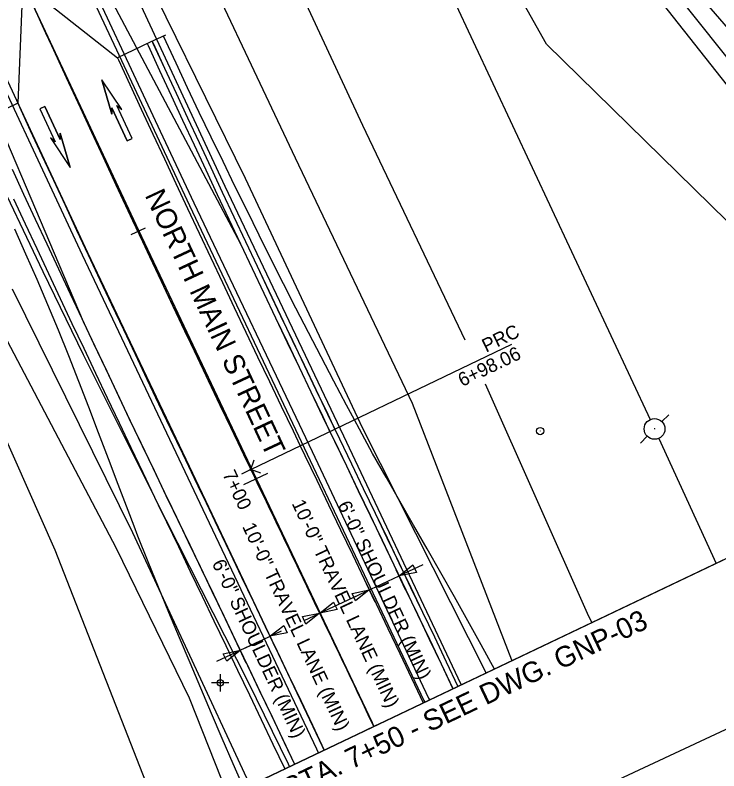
# Model space of a CAD drawing. Extents: x 1040364 to 1041050, y 1127298 to 1128100.
# Drawn here: x 1040771.9 to 1040900.2, y 1127434.3 to 1127572.2 of the extents above; entities that cross this region are included whole.
import ezdxf

# ---------------------------------------------------------------- set-up
doc = ezdxf.new("R2010")
doc.units = 0
for name, color, linetype in [('AC_P', 7, 'Continuous'), ('ACP_P', 7, 'Continuous'), ('ACSC_P_T', 7, 'Continuous'), ('ACSCT_P', 7, 'Continuous'), ('ACSR_P_T', 7, 'Continuous'), ('ACSRT_P', 7, 'Continuous'), ('clip boundary', 7, 'Continuous'), ('DELB', 7, 'Continuous'), ('LELB', 7, 'Continuous'), ('LFILL_P', 7, 'Continuous'), ('LPST', 7, 'Continuous'), ('NML_P', 7, 'Continuous'), ('NML_P_T', 7, 'Continuous'), ('O_Details_Dimensions_Extension_Lines_P', 7, 'Continuous'), ('O_Details_Text Title and Subtitle Proposed_P_T', 7, 'Continuous'), ('PE', 7, 'Continuous'), ('PE_P', 7, 'Continuous'), ('PET_P', 7, 'Continuous'), ('PSCL_P', 7, 'Continuous'), ('RBS_P', 7, 'Continuous'), ('RGB_P', 7, 'Continuous'), ('RGC', 7, 'Continuous'), ('S', 7, 'Continuous'), ('SHEET_BORDER', 7, 'Continuous'), ('STFBY', 7, 'Continuous'), ('STFBY_P', 7, 'Continuous'), ('STSEW', 7, 'Continuous'), ('STSEY_P_T', 7, 'Continuous'), ('UEO', 7, 'Continuous'), ('UP', 7, 'Continuous')]:
    doc.layers.add(name, color=color, linetype=linetype)

msp = doc.modelspace()

# ---------------------------------------------------------------- linework, layer by layer
at = {"layer": 'AC_P'}
for centre, radius, start, end in [((1045321.32, 1129655.39), 5000, 200.40109, 205.67201), ((1027295.55, 1120991.01), 15000, 25.473615, 25.672008)]:
    msp.add_arc(centre, radius, start, end, dxfattribs=at)
at = {"layer": 'ACP_P'}
for p, q in [((1040814.88, 1127489.29), (1040815.5, 1127491.07)), ((1040814.88, 1127489.29), (1040813.18, 1127488.48)), ((1040816.66, 1127488.67), (1040814.88, 1127489.29))]:
    msp.add_line(p, q, dxfattribs=at)
msp.add_circle((1040814.88, 1127489.29), 0.154, dxfattribs=at)
at = {"layer": 'ACSCT_P'}
msp.add_lwpolyline([(1040814.88, 1127489.29), (1040862.47, 1127512.17)], dxfattribs=at)
at = {"layer": 'ACSRT_P'}
for points in [[(1040795.57, 1127533.32), (1040792.96, 1127532.1)], [(1040817.88, 1127488.58), (1040813.55, 1127486.5)], [(1040838.6, 1127443.06), (1040836, 1127441.82)]]:
    msp.add_lwpolyline(points, dxfattribs=at)
at = {"layer": 'clip boundary'}
msp.add_lwpolyline([(1040504.79, 1127904.67), (1040760.34, 1127999.71), (1040984.84, 1127512.73), (1040710.81, 1127382.18)], close=True, dxfattribs=at)
at = {"layer": 'DELB'}
for points in [[(1040843.18, 1127644.23), (1040860.99, 1127621.14), (1040885.95, 1127579.46), (1040912.52, 1127545.72), (1040920.83, 1127536.22), (1040925.1, 1127538.74), (1040927.41, 1127544.76), (1040923.92, 1127547.39), (1040891.85, 1127585.59), (1040869.69, 1127619.79), (1040852.79, 1127648.53), (1040846.95, 1127649.39), (1040843.18, 1127644.23)], [(1040848.54, 1127644.26), (1040847.59, 1127642.87), (1040862.62, 1127622.4), (1040888.43, 1127581.11), (1040915.18, 1127547.57), (1040922.33, 1127543.57), (1040922.43, 1127546.09), (1040889.43, 1127584.33), (1040867.88, 1127618.82), (1040850.55, 1127644.3), (1040848.54, 1127644.26)]]:
    msp.add_lwpolyline(points, dxfattribs=at)
at = {"layer": 'LELB'}
for points in [[(1040810.73, 1127429.78), (1040803.7, 1127447.62), (1040790.28, 1127475.04), (1040767.31, 1127518.61), (1040755.95, 1127542.69), (1040738.89, 1127579.03), (1040723.86, 1127612.81), (1040706.92, 1127651.68), (1040695, 1127676.62), (1040683.43, 1127703.39), (1040670.93, 1127728.26), (1040660.81, 1127750.01), (1040651.71, 1127772.02), (1040637.02, 1127804.07), (1040629.69, 1127830.98), (1040616.26, 1127871.74), (1040612.35, 1127873.83), (1040609.66, 1127871.77), (1040608.53, 1127867.34), (1040606.04, 1127852.48)], [(1040713.7, 1127825.26), (1040727.06, 1127775.17), (1040743.3, 1127730.12), (1040761.87, 1127681.6), (1040780.54, 1127637.65), (1040801.46, 1127591.59), (1040822.93, 1127546.17), (1040844.27, 1127501.4), (1040862.43, 1127454.57), (1040862.49, 1127454.44)], [(1040733.39, 1127778.3), (1040755.39, 1127731.1), (1040772.83, 1127689.2), (1040794.16, 1127643.36), (1040815.07, 1127595.54), (1040835.22, 1127552.16), (1040853.9, 1127512.99)], [(1040857.81, 1127452.21), (1040835.32, 1127496.78), (1040813.91, 1127542.4), (1040792.2, 1127586.64), (1040772.38, 1127632.65), (1040752.78, 1127677.66), (1040736.76, 1127724.02), (1040719.71, 1127771.8)], [(1040931.31, 1127487.23), (1040907.7, 1127528.76), (1040868.8, 1127566.91), (1040846.16, 1127607.17), (1040843.18, 1127644.23)], [(1040814.73, 1127431.69), (1040814.14, 1127433.03), (1040793.33, 1127477.77), (1040771.38, 1127522.24)], [(1040759.32, 1127519.12), (1040779.14, 1127474.66), (1040797.84, 1127426.8), (1040798.87, 1127424.14)], [(1040857.64, 1127504.94), (1040876.45, 1127462.54), (1040877.08, 1127461.4)]]:
    msp.add_lwpolyline(points, dxfattribs=at)
at = {"layer": 'LFILL_P'}
for points in [[(1040859.29, 1127452.92), (1040856.87, 1127457.31), (1040854.44, 1127461.7), (1040851.99, 1127466.08), (1040849.52, 1127470.45), (1040847.04, 1127474.82), (1040844.54, 1127479.17), (1040842.03, 1127483.52), (1040839.55, 1127487.89), (1040837.07, 1127492.25), (1040834.67, 1127496.65), (1040833.75, 1127498.36), (1040832.32, 1127501.06), (1040829.99, 1127505.46), (1040827.68, 1127509.88), (1040825.38, 1127514.3), (1040823.1, 1127518.73), (1040820.84, 1127523.17), (1040818.6, 1127527.62), (1040816.37, 1127532.07), (1040814.17, 1127536.54), (1040811.97, 1127541.01), (1040809.79, 1127545.49), (1040807.62, 1127549.97), (1040805.47, 1127554.47), (1040803.34, 1127558.97), (1040801.22, 1127563.47), (1040798.92, 1127568.38)], [(1040771.75, 1127533.24), (1040773.79, 1127528.65), (1040775.81, 1127524.05), (1040777.78, 1127519.43), (1040779.73, 1127514.8), (1040781.58, 1127510.12), (1040783.41, 1127505.43), (1040785.23, 1127500.74), (1040787.04, 1127496.04), (1040788.84, 1127491.33), (1040790.63, 1127486.62), (1040792.43, 1127481.91), (1040793.53, 1127479.03), (1040794.22, 1127477.22), (1040796.05, 1127472.55), (1040797.94, 1127467.93), (1040799.86, 1127463.31), (1040801.78, 1127458.69), (1040803.71, 1127454.09), (1040805.66, 1127449.48), (1040807.61, 1127444.88), (1040809.58, 1127440.29), (1040811.57, 1127435.71), (1040813.59, 1127431.15)]]:
    msp.add_lwpolyline(points, dxfattribs=at)
at = {"layer": 'LPST'}
for p, q in [((1040867.65, 1127496.35), (1040867.62, 1127496.32)), ((1040867.62, 1127496.35), (1040867.65, 1127496.32))]:
    msp.add_line(p, q, dxfattribs=at)
msp.add_circle((1040867.64, 1127496.33), 0.658, dxfattribs=at)
at = {"layer": 'NML_P'}
msp.add_line((1040710.81, 1127382.18), (1040984.84, 1127512.73), dxfattribs=at)
at = {"layer": 'O_Details_Dimensions_Extension_Lines_P'}
for p, q in [((1040843.1, 1127467.37), (1040841.39, 1127471.03)), ((1040846.27, 1127471.93), (1040841.92, 1127469.9)), ((1040833.65, 1127466.03), (1040841.92, 1127469.9)), ((1040837.54, 1127465.09), (1040835.96, 1127468.49)), ((1040827.42, 1127463.12), (1040834.31, 1127466.34)), ((1040828.7, 1127460.4), (1040826.9, 1127464.26)), ((1040824.59, 1127461.8), (1040827.46, 1127463.14)), ((1040813.87, 1127456.79), (1040820.45, 1127459.86)), ((1040819.47, 1127456.53), (1040817.83, 1127460.02)), ((1040814.02, 1127454), (1040812.39, 1127457.5)), ((1040812.93, 1127456.34), (1040816.55, 1127458.05)), ((1040808.64, 1127454.33), (1040812.99, 1127456.36))]:
    msp.add_line(p, q, dxfattribs=at)
for points in [[(1040845.07, 1127470.54), (1040841.92, 1127469.9), (1040844.44, 1127471.9)], [(1040833.33, 1127466.71), (1040836.48, 1127467.36), (1040833.97, 1127465.35)], [(1040830.61, 1127463.78), (1040827.46, 1127463.14), (1040829.97, 1127465.14)], [(1040824.27, 1127462.48), (1040827.42, 1127463.12), (1040824.91, 1127461.12)], [(1040821.51, 1127459.53), (1040818.36, 1127458.89), (1040820.88, 1127460.89)], [(1040809.84, 1127455.72), (1040812.99, 1127456.36), (1040810.48, 1127454.36)]]:
    msp.add_lwpolyline(points, close=True, dxfattribs=at)
at = {"layer": 'O_Details_Text Title and Subtitle Proposed_P_T'}
for p, q in [((1040789.5, 1127554.17), (1040787.7, 1127560.39)), ((1040791.32, 1127555.01), (1040787.7, 1127560.39)), ((1040776.83, 1127555.31), (1040776.8, 1127555.3)), ((1040776.84, 1127555.29), (1040776.81, 1127555.28)), ((1040790.44, 1127555.71), (1040791.32, 1127555.01)), ((1040780.11, 1127550.66), (1040781.91, 1127544.44)), ((1040778.29, 1127549.81), (1040781.91, 1127544.44)), ((1040779.17, 1127549.12), (1040778.29, 1127549.81)), ((1040792.77, 1127549.53), (1040792.8, 1127549.55)), ((1040792.78, 1127549.52), (1040792.81, 1127549.53))]:
    msp.add_line(p, q, dxfattribs=at)
at = {"layer": 'PE'}
for points in [[(1040632.25, 1127952.07), (1040649.62, 1127906.04), (1040655.5, 1127890.52), (1040667.36, 1127859.52), (1040679.42, 1127828.44), (1040685.53, 1127812.93), (1040691.68, 1127797.52), (1040704.12, 1127766.75), (1040723.07, 1127720.54), (1040735.94, 1127689.83), (1040742.48, 1127674.51), (1040755.79, 1127643.96), (1040762.56, 1127628.73), (1040769.44, 1127613.48), (1040783.38, 1127583.06), (1040797.39, 1127552.96), (1040804.47, 1127537.94), (1040826.05, 1127492.6), (1040847.29, 1127447.58), (1040847.43, 1127447.27)], [(1040827.22, 1127437.64), (1040826.9, 1127438.31), (1040805.61, 1127483.11), (1040784.16, 1127528.43), (1040762.74, 1127574.12), (1040748.8, 1127604.56), (1040741.94, 1127619.83), (1040735.2, 1127635.03), (1040721.93, 1127665.52), (1040708.68, 1127696.59), (1040702.17, 1127712.18), (1040695.93, 1127727.39), (1040683.59, 1127757.86), (1040671.21, 1127788.47), (1040665.07, 1127803.8), (1040658.98, 1127819.2), (1040646.94, 1127850.06), (1040634.62, 1127882.06), (1040628.54, 1127898.1), (1040611.22, 1127944.25)]]:
    msp.add_lwpolyline(points, dxfattribs=at)
at = {"layer": 'PE_P'}
for points in [[(1040795.88, 1127567.13), (1040796.11, 1127566.68), (1040798.23, 1127562.09), (1040800.32, 1127557.57), (1040802.42, 1127553.05), (1040804.53, 1127548.53), (1040806.64, 1127544.01), (1040808.75, 1127539.5), (1040810.87, 1127534.99), (1040812.99, 1127530.48), (1040815.12, 1127525.97), (1040817.25, 1127521.47), (1040819.39, 1127516.96), (1040821.53, 1127512.46), (1040823.67, 1127507.96), (1040825.82, 1127503.47), (1040827.98, 1127498.97), (1040829.3, 1127496.22), (1040830.14, 1127494.47), (1040832.31, 1127489.96), (1040834.47, 1127485.45), (1040836.64, 1127480.94), (1040838.8, 1127476.42), (1040840.96, 1127471.91), (1040843.12, 1127467.39), (1040845.28, 1127462.88), (1040847.43, 1127458.36), (1040849.59, 1127453.84), (1040851.74, 1127449.32)], [(1040771.3, 1127544.1), (1040773.41, 1127539.55), (1040775.53, 1127535), (1040777.65, 1127530.46), (1040779.78, 1127525.92), (1040781.91, 1127521.37), (1040784.05, 1127516.84), (1040786.19, 1127512.3), (1040788.33, 1127507.77), (1040790.48, 1127503.23), (1040792.64, 1127498.7), (1040794.8, 1127494.18), (1040796.96, 1127489.65), (1040799.13, 1127485.13), (1040800.46, 1127482.36), (1040801.3, 1127480.61), (1040803.46, 1127476.11), (1040805.62, 1127471.61), (1040807.78, 1127467.11), (1040809.94, 1127462.6), (1040812.09, 1127458.1), (1040814.25, 1127453.59), (1040816.4, 1127449.08), (1040818.55, 1127444.58), (1040820.7, 1127440.07), (1040822.85, 1127435.56)]]:
    msp.add_lwpolyline(points, dxfattribs=at)
at = {"layer": 'PET_P'}
for points in [[(1040790.52, 1127564.43), (1040790.7, 1127564.07), (1040792.78, 1127559.57), (1040794.88, 1127555.04), (1040796.98, 1127550.52), (1040799.09, 1127545.99), (1040801.2, 1127541.47), (1040803.32, 1127536.95), (1040805.44, 1127532.44), (1040807.56, 1127527.92), (1040809.69, 1127523.41), (1040811.83, 1127518.9), (1040813.97, 1127514.39), (1040816.11, 1127509.88), (1040818.26, 1127505.38), (1040820.41, 1127500.88), (1040822.57, 1127496.38), (1040823.89, 1127493.62), (1040824.73, 1127491.87), (1040826.9, 1127487.36), (1040829.06, 1127482.85), (1040831.22, 1127478.34), (1040833.39, 1127473.83), (1040835.55, 1127469.32), (1040837.71, 1127464.8), (1040839.86, 1127460.29), (1040842.02, 1127455.77), (1040844.17, 1127451.26), (1040846.32, 1127446.74)], [(1040772.35, 1127556.12), (1040774.63, 1127551.17), (1040776.74, 1127546.62), (1040778.85, 1127542.08), (1040780.97, 1127537.54), (1040783.09, 1127533), (1040785.21, 1127528.46), (1040787.34, 1127523.93), (1040789.47, 1127519.39), (1040791.61, 1127514.86), (1040793.75, 1127510.33), (1040795.9, 1127505.81), (1040798.05, 1127501.28), (1040800.21, 1127496.76), (1040802.37, 1127492.24), (1040804.54, 1127487.72), (1040805.86, 1127484.96), (1040806.7, 1127483.21), (1040808.87, 1127478.71), (1040811.03, 1127474.2), (1040813.19, 1127469.7), (1040815.35, 1127465.19), (1040817.51, 1127460.69), (1040819.66, 1127456.18), (1040821.82, 1127451.67), (1040823.97, 1127447.16), (1040826.12, 1127442.65), (1040828.27, 1127438.14)]]:
    msp.add_lwpolyline(points, dxfattribs=at)
at = {"layer": 'PSCL_P'}
for p, q in [((1040773.26, 1127578.08), (1040772.35, 1127556.12)), ((1040773.26, 1127578.08), (1040790.52, 1127564.43)), ((1040796.4, 1127567.22), (1040790.52, 1127564.43)), ((1040772.35, 1127556.12), (1040766.62, 1127553.47))]:
    msp.add_line(p, q, dxfattribs=at)
at = {"layer": 'RBS_P'}
msp.add_line((1040799.31, 1127568.56), (1040796.4, 1127567.22), dxfattribs=at)
for points in [[(1040796.79, 1127567.55), (1040797.01, 1127567.1), (1040799.13, 1127562.51), (1040801.23, 1127557.99), (1040803.33, 1127553.47), (1040805.43, 1127548.95), (1040807.54, 1127544.44), (1040809.66, 1127539.92), (1040811.78, 1127535.41), (1040813.9, 1127530.9), (1040816.03, 1127526.4), (1040818.16, 1127521.89), (1040820.29, 1127517.39), (1040822.43, 1127512.89), (1040824.58, 1127508.39), (1040826.73, 1127503.89), (1040828.88, 1127499.4), (1040830.2, 1127496.65), (1040831.04, 1127494.9), (1040833.21, 1127490.38), (1040835.38, 1127485.87), (1040837.54, 1127481.36), (1040839.7, 1127476.84), (1040841.86, 1127472.33), (1040844.02, 1127467.81), (1040846.18, 1127463.3), (1040848.34, 1127458.78), (1040850.49, 1127454.26), (1040852.64, 1127449.75)], [(1040771.6, 1127538.71), (1040773.72, 1127534.16), (1040775.84, 1127529.61), (1040777.97, 1127525.07), (1040780.1, 1127520.52), (1040782.24, 1127515.98), (1040784.38, 1127511.45), (1040786.52, 1127506.91), (1040788.68, 1127502.38), (1040790.83, 1127497.84), (1040792.99, 1127493.31), (1040795.16, 1127488.79), (1040797.32, 1127484.26), (1040798.65, 1127481.49), (1040799.49, 1127479.75), (1040801.66, 1127475.25), (1040803.82, 1127470.74), (1040805.97, 1127466.24), (1040808.13, 1127461.74), (1040810.29, 1127457.23), (1040812.44, 1127452.73), (1040814.6, 1127448.22), (1040816.75, 1127443.71), (1040818.9, 1127439.21), (1040821.05, 1127434.7)]]:
    msp.add_lwpolyline(points, dxfattribs=at)
at = {"layer": 'RGB_P'}
for points in [[(1040784.95, 1127583.36), (1040812.99, 1127530.49), (1040815.11, 1127525.99), (1040817.24, 1127521.49), (1040819.38, 1127516.99), (1040821.51, 1127512.49), (1040823.66, 1127508), (1040825.81, 1127503.5), (1040827.96, 1127499.01), (1040829.28, 1127496.27), (1040830.12, 1127494.52), (1040832.29, 1127490), (1040834.45, 1127485.49), (1040836.62, 1127480.97), (1040838.78, 1127476.46), (1040840.94, 1127471.94), (1040843.1, 1127467.43), (1040845.26, 1127462.91), (1040847.42, 1127458.39), (1040849.57, 1127453.87), (1040851.73, 1127449.35), (1040851.74, 1127449.32)], [(1040760.67, 1127571.78), (1040784.28, 1127516.33), (1040786.42, 1127511.79), (1040788.57, 1127507.25), (1040790.72, 1127502.72), (1040792.88, 1127498.18), (1040795.04, 1127493.65), (1040797.21, 1127489.12), (1040799.38, 1127484.59), (1040800.71, 1127481.82), (1040801.55, 1127480.08), (1040803.71, 1127475.57), (1040805.87, 1127471.07), (1040808.03, 1127466.57), (1040810.19, 1127462.07), (1040812.34, 1127457.56), (1040814.5, 1127453.06), (1040816.65, 1127448.56), (1040818.8, 1127444.05), (1040820.95, 1127439.54), (1040822.85, 1127435.56)]]:
    msp.add_lwpolyline(points, dxfattribs=at)
at = {"layer": 'RGC'}
for points in [[(1040821.91, 1127435.11), (1040821.71, 1127435.54), (1040814.44, 1127450.47), (1040799.42, 1127480.1), (1040784.36, 1127510.25), (1040776.98, 1127525.39), (1040767.39, 1127545.45), (1040762.66, 1127555.51), (1040755.68, 1127570.65), (1040748.81, 1127585.88), (1040735.39, 1127616.49), (1040722.27, 1127647.33), (1040715.84, 1127662.8), (1040696.64, 1127709.35), (1040677.37, 1127755.44), (1040658.12, 1127800.96), (1040638.6, 1127847.62), (1040631.97, 1127863.41)], [(1040714.38, 1127770.91), (1040732.29, 1127723.82), (1040749.62, 1127677.89), (1040755.63, 1127662.08), (1040762.02, 1127646.41), (1040768.42, 1127631.69), (1040775.21, 1127616.41), (1040789.21, 1127586.06), (1040810.12, 1127540.99), (1040831.75, 1127495.43), (1040853.16, 1127450.13), (1040853.21, 1127450.02)]]:
    msp.add_lwpolyline(points, dxfattribs=at)
at = {"layer": 'S'}
for p, q in [((1040809.3, 1127451.99), (1040809.3, 1127448.84)), ((1040810.87, 1127450.41), (1040807.72, 1127450.41))]:
    msp.add_line(p, q, dxfattribs=at)
msp.add_circle((1040809.3, 1127450.41), 0.591, dxfattribs=at)
at = {"layer": 'SHEET_BORDER'}
msp.add_lwpolyline([(1040652.69, 1127325.65), (1040649.37, 1127326.86), (1040384.85, 1127893.12), (1040386.05, 1127896.45), (1040761.49, 1128071.82), (1040764.81, 1128070.62), (1041029.33, 1127504.35), (1041028.12, 1127501.03)], close=True, dxfattribs=at)
at = {"layer": 'STFBY'}
msp.add_lwpolyline([(1040837.33, 1127442.46), (1040837.03, 1127443.08), (1040815.99, 1127487.47), (1040794.41, 1127532.94), (1040773.27, 1127578.07), (1040759.07, 1127608.84), (1040752.08, 1127624.28), (1040745.3, 1127639.51), (1040732.01, 1127670.09), (1040712.44, 1127716.22), (1040699.8, 1127746.64), (1040693.6, 1127761.89), (1040675.04, 1127808.28), (1040673.1, 1127813.03)], dxfattribs=at)
at = {"layer": 'STFBY_P'}
for points in [[(1040775.34, 1127573.54), (1040777.43, 1127568.99), (1040779.52, 1127564.45), (1040781.61, 1127559.91), (1040783.71, 1127555.37), (1040785.81, 1127550.83), (1040787.92, 1127546.3), (1040790.03, 1127541.77), (1040792.14, 1127537.24), (1040794.26, 1127532.71), (1040796.39, 1127528.18), (1040798.52, 1127523.66), (1040800.65, 1127519.14), (1040802.79, 1127514.62), (1040804.93, 1127510.1), (1040807.08, 1127505.58), (1040809.23, 1127501.07), (1040811.39, 1127496.56), (1040813.55, 1127492.05), (1040814.88, 1127489.29), (1040815.72, 1127487.54), (1040817.88, 1127483.04), (1040820.05, 1127478.53), (1040822.21, 1127474.02), (1040824.37, 1127469.51), (1040826.53, 1127465), (1040828.68, 1127460.49), (1040830.84, 1127455.98), (1040832.99, 1127451.47), (1040835.15, 1127446.95), (1040837.3, 1127442.44)], [(1040796.79, 1127567.54), (1040797.02, 1127567.09), (1040799.14, 1127562.51), (1040801.23, 1127557.98), (1040803.33, 1127553.46), (1040805.44, 1127548.95), (1040807.55, 1127544.43), (1040809.66, 1127539.92), (1040811.78, 1127535.4), (1040813.9, 1127530.9), (1040816.03, 1127526.39), (1040818.16, 1127521.88), (1040820.3, 1127517.38), (1040822.44, 1127512.88), (1040824.58, 1127508.38), (1040826.73, 1127503.88), (1040828.89, 1127499.39), (1040830.21, 1127496.64), (1040831.05, 1127494.89), (1040833.22, 1127490.38), (1040835.38, 1127485.86), (1040837.54, 1127481.35), (1040839.71, 1127476.84), (1040841.87, 1127472.32), (1040844.03, 1127467.81), (1040846.19, 1127463.29), (1040848.34, 1127458.77), (1040850.5, 1127454.26), (1040852.64, 1127449.75)]]:
    msp.add_lwpolyline(points, dxfattribs=at)
at = {"layer": 'STSEW'}
for points in [[(1040631.23, 1127951.69), (1040648.51, 1127905.59), (1040654.39, 1127890.06), (1040666.38, 1127859.09), (1040684.56, 1127812.57), (1040690.71, 1127797.15), (1040703.13, 1127766.35), (1040715.7, 1127735.48), (1040722.06, 1127720.07), (1040728.5, 1127704.72), (1040741.59, 1127674.11), (1040754.93, 1127643.58), (1040761.69, 1127628.35), (1040768.56, 1127613.09), (1040782.51, 1127582.66), (1040803.66, 1127537.47), (1040825.13, 1127492.13), (1040846.44, 1127447.18), (1040846.59, 1127446.87)], [(1040828.27, 1127438.14), (1040827.96, 1127438.8), (1040806.65, 1127483.62), (1040785.12, 1127528.86), (1040763.78, 1127574.53), (1040749.77, 1127604.92), (1040742.86, 1127620.16), (1040736.1, 1127635.32), (1040722.83, 1127665.76), (1040716.16, 1127681.33), (1040702.99, 1127712.55), (1040690.38, 1127742.93), (1040684.16, 1127758.16), (1040671.9, 1127788.75), (1040665.82, 1127804.07), (1040659.73, 1127819.47), (1040647.66, 1127850.31), (1040635.42, 1127882.35), (1040629.38, 1127898.4), (1040612.07, 1127944.56)]]:
    msp.add_lwpolyline(points, dxfattribs=at)
at = {"layer": 'STSEY_P_T'}
for p, q in [((1040791.32, 1127555.01), (1040787.7, 1127560.39)), ((1040787.7, 1127560.39), (1040789.5, 1127554.17)), ((1040777.28, 1127555.52), (1040776.38, 1127555.1)), ((1040776.38, 1127555.1), (1040779.17, 1127549.12)), ((1040776.38, 1127555.1), (1040779.17, 1127549.12)), ((1040777.28, 1127555.52), (1040780.08, 1127549.54)), ((1040780.08, 1127549.54), (1040777.28, 1127555.52)), ((1040789.53, 1127555.28), (1040789.5, 1127554.17)), ((1040789.5, 1127554.17), (1040789.53, 1127555.28)), ((1040792.33, 1127549.3), (1040789.53, 1127555.28)), ((1040789.53, 1127555.28), (1040792.33, 1127549.3)), ((1040793.23, 1127549.73), (1040790.44, 1127555.71)), ((1040793.23, 1127549.73), (1040790.44, 1127555.71)), ((1040790.44, 1127555.71), (1040791.32, 1127555.01)), ((1040780.08, 1127549.54), (1040780.11, 1127550.66)), ((1040780.11, 1127550.66), (1040780.08, 1127549.54)), ((1040781.91, 1127544.44), (1040780.11, 1127550.66)), ((1040779.17, 1127549.12), (1040778.29, 1127549.81)), ((1040778.29, 1127549.81), (1040781.91, 1127544.44)), ((1040792.33, 1127549.3), (1040793.23, 1127549.73))]:
    msp.add_line(p, q, dxfattribs=at)
for points in [[(1040777.28, 1127555.52), (1040776.83, 1127555.31), (1040776.38, 1127555.1)], [(1040792.33, 1127549.3), (1040792.78, 1127549.52), (1040793.23, 1127549.73)]]:
    msp.add_lwpolyline(points, dxfattribs=at)
at = {"layer": 'UEO'}
for points in [[(1040794.43, 1127697.72), (1040887.71, 1127498.43)], [(1040889.3, 1127495), (1040899.76, 1127472.2)]]:
    msp.add_lwpolyline(points, dxfattribs=at)
at = {"layer": 'UP'}
for p, q in [((1040889.84, 1127498.06), (1040891.09, 1127499.32)), ((1040888.57, 1127496.72), (1040888.45, 1127496.72)), ((1040888.51, 1127496.78), (1040888.51, 1127496.66)), ((1040887.18, 1127495.38), (1040885.93, 1127494.12))]:
    msp.add_line(p, q, dxfattribs=at)
msp.add_circle((1040888.51, 1127496.72), 1.89, dxfattribs=at)

# ---------------------------------------------------------------- texts
at = {"layer": 'ACSC_P_T'}
for s, p in [('PRC', (1040857.78, 1127510.61)), ('6+98.06', (1040853.42, 1127504.36))]:
    msp.add_text(s, height=2.496, rotation=25.672, dxfattribs=at).set_placement(p)
at = {"layer": 'ACSR_P_T'}
msp.add_text('7+00', height=2.496, rotation=295.6646, dxfattribs=at).set_placement((1040809.63, 1127488.46))
at = {"layer": 'NML_P_T'}
msp.add_text('MATCHLINE STA. 7+50 - SEE DWG. GNP-03', height=3.744, rotation=25.4736, dxfattribs=at).set_placement((1040794.55, 1127416.18))
at = {"layer": 'O_Details_Dimensions_Extension_Lines_P'}
for s, p in [('10\'-0" TRAVEL LANE (MIN)', (1040822.27, 1127483.15)), ('6\'-0" SHOULDER (MIN)', (1040830.63, 1127482.88)), ('10\'-0" TRAVEL LANE (MIN)', (1040813.24, 1127478.93)), ('6\'-0" SHOULDER (MIN)', (1040807.71, 1127472.22))]:
    msp.add_text(s, height=2.5008, rotation=295.0387, dxfattribs=at).set_placement(p)
at = {"layer": 'O_Details_Text Title and Subtitle Proposed_P_T'}
msp.add_text('NORTH MAIN STREET', height=3.7536, rotation=295.0387, dxfattribs=at).set_placement((1040795.46, 1127539.36))

doc.saveas('drawing.dxf')
